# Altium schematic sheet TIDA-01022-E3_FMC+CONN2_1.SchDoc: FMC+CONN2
size 431 x 279 mm; Date: Not shown in title block; ApprovedBy: Not shown in title block; CheckedBy: Not shown in title block; Author: Not shown in title block; CompanyName: Not shown in title block; DrawnBy: Avinash N; Engineer: Not shown in title block; Organization: Not shown in title block; Address1: Not shown in title block; Address2: Not shown in title block; Address3: Not shown in title block; Address4: Not shown in title block; DocumentNumber: 1; Revision: Use project parameter SCH_Rev; SheetNumber: 19; SheetTotal: 26; PageSetup: Record=PageOptions¦CenterHorizontal=True¦CenterVertical=True¦PrintScale=1.00¦XCorrection=1.00¦YCorrection=1.00¦PrintKind=0¦BorderSize=5000000¦LeftOffset=0¦BottomOffset=0¦Orientation=2¦PaperLength=1000¦PaperWidth=1000¦Scale=100¦PaperSource=15¦PrintQuality=600¦MediaType=1¦DitherType=10¦PaperKind=Letter¦PrintScaleMode=1
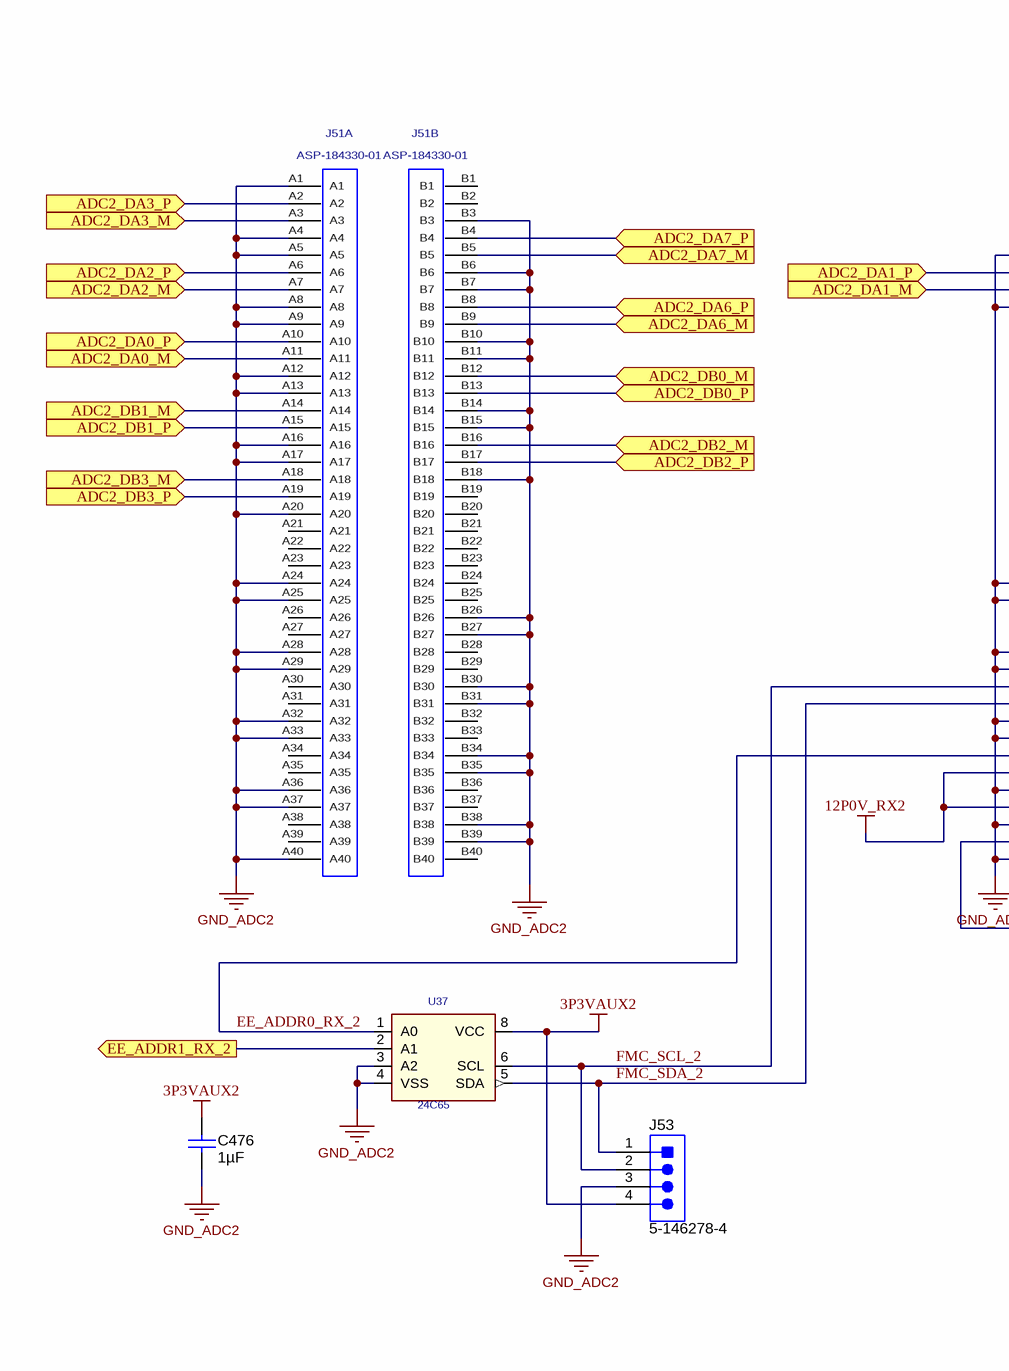
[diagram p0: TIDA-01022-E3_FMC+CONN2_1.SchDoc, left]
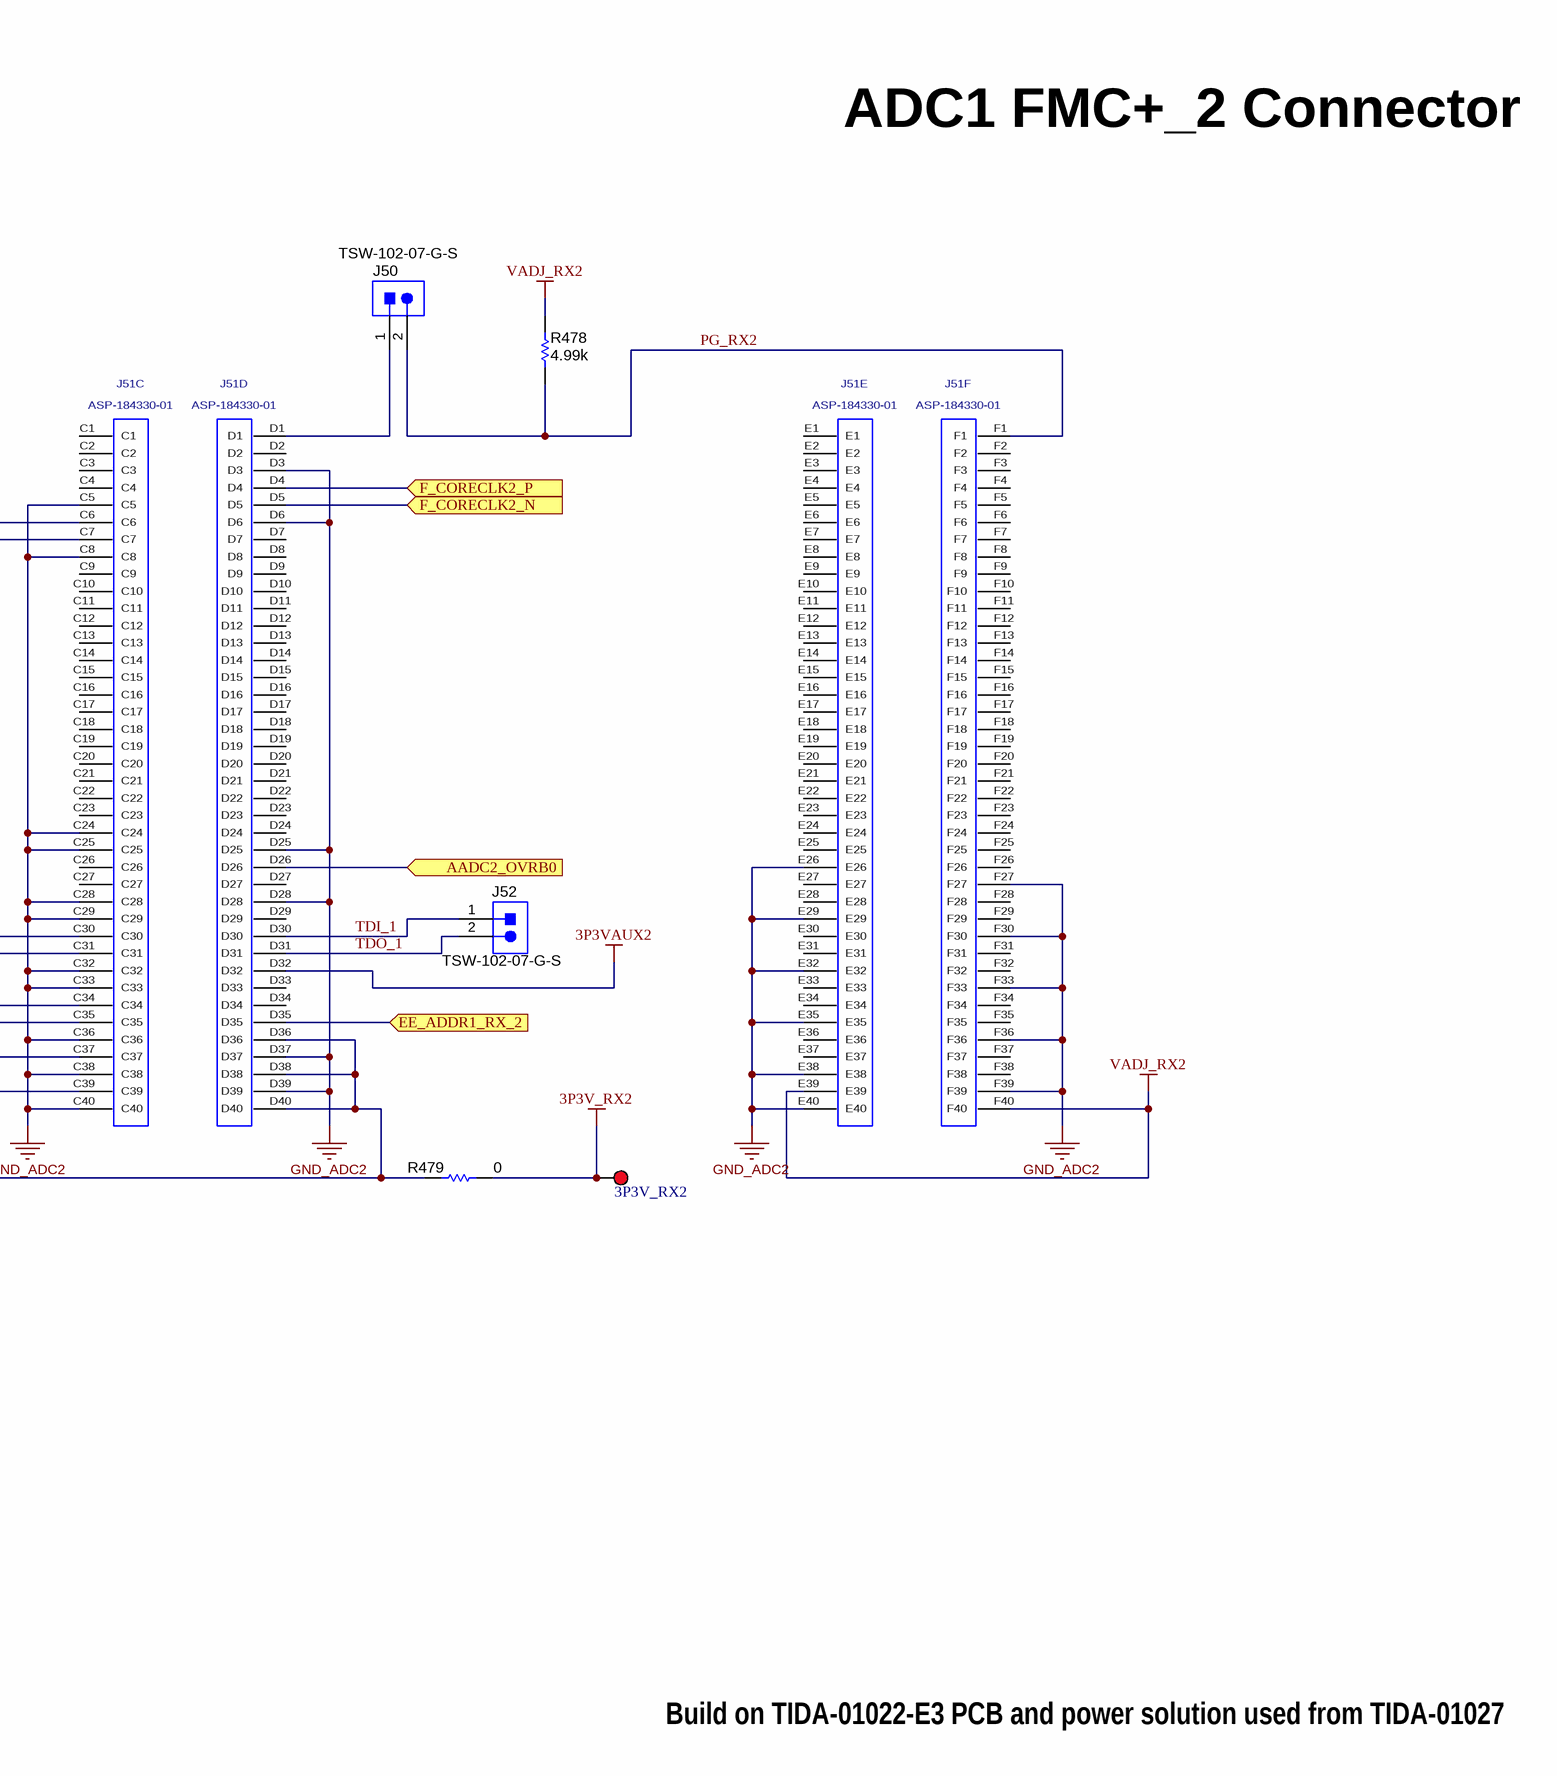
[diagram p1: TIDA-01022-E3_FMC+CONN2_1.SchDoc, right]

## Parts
3P3V_RX2  5000  [Keystone5000]  (value not drawn)
C476  ValueDisplayed: 1µF  [0603]  (hidden comment: C1608X5R1A105K080AC)
J50  TSW-102-07-G-S  [TSW-102-07-G-S]
J51  ASP-184330-01  [ASP-184330-01]  (parts A,B,C,D,E,F of 14)
J52  TSW-102-07-G-S  [TSW-102-07-G-S]
J53  5-146278-4  [TE_5-146278-4]
R478  ValueDisplayed: 4.99k  [0402]  (hidden comment: CRCW04024K99FKED)
R479  ValueDisplayed: 0  [0402]  (hidden comment: CRCW04020000Z0ED)
U37  24C65  [SOIC127P800X216-8N]

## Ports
AADC2_OVRB0 (in), ADC2_DA0_M (in), ADC2_DA0_P (in), ADC2_DA1_M (in), ADC2_DA1_P (in), ADC2_DA2_M (in), ADC2_DA2_P (in), ADC2_DA3_M (in), ADC2_DA3_P (in), ADC2_DA6_M (in), ADC2_DA6_P (in), ADC2_DA7_M (in), ADC2_DA7_P (in), ADC2_DB0_M (in), ADC2_DB0_P (in), ADC2_DB1_M (in), ADC2_DB1_P (in), ADC2_DB2_M (in), ADC2_DB2_P (in), ADC2_DB3_M (in), ADC2_DB3_P (in), EE_ADDR1_RX_2 (in), EE_ADDR1_RX_2 (out), F_CORECLK2_N (in), F_CORECLK2_P (in)

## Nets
3P3V_RX2: 3P3V_RX2.1 R479.1
3P3VAUX2: C476.1 J51.D32 J53.4 U37.8(VCC)
12P0V_RX2: J51.C35 J51.C37
GND_ADC2: C476.2 J51.A1 J51.A4 J51.A5 J51.A8 J51.A9 J51.A12 J51.A13 J51.A16 J51.A17 J51.A20 J51.A24 J51.A25 J51.A28 J51.A29 J51.A32 J51.A33 J51.A36 J51.A37 J51.A40 J51.B3 J51.B6 J51.B7 J51.B10 J51.B11 J51.B14 J51.B15 J51.B18 J51.B26 J51.B27 J51.B30 J51.B31 J51.B34 J51.B35 J51.B38 J51.B39 J51.C5 J51.C8 J51.C24 J51.C25 J51.C28 J51.C29 J51.C32 J51.C33 J51.C36 J51.C38 J51.C40 J51.D3 J51.D6 J51.D25 J51.D28 J51.D37 J51.D39 J51.E26 J51.E29 J51.E32 J51.E35 J51.E38 J51.E40 J51.F27 J51.F30 J51.F33 J51.F36 J51.F39 J53.3 U37.3(A2) U37.4(VSS)
VADJ_RX2: J51.E39 J51.F40 R478.2
AADC2_OVRB0: J51.D26 ; port AADC2_OVRB0
ADC2_DA0_M: J51.A11 ; port ADC2_DA0_M
ADC2_DA0_P: J51.A10 ; port ADC2_DA0_P
ADC2_DA1_M: J51.C7 ; port ADC2_DA1_M
ADC2_DA1_P: J51.C6 ; port ADC2_DA1_P
ADC2_DA2_M: J51.A7 ; port ADC2_DA2_M
ADC2_DA2_P: J51.A6 ; port ADC2_DA2_P
ADC2_DA3_M: J51.A3 ; port ADC2_DA3_M
ADC2_DA3_P: J51.A2 ; port ADC2_DA3_P
ADC2_DA6_M: J51.B9 ; port ADC2_DA6_M
ADC2_DA6_P: J51.B8 ; port ADC2_DA6_P
ADC2_DA7_M: J51.B5 ; port ADC2_DA7_M
ADC2_DA7_P: J51.B4 ; port ADC2_DA7_P
ADC2_DB0_M: J51.B12 ; port ADC2_DB0_M
ADC2_DB0_P: J51.B13 ; port ADC2_DB0_P
ADC2_DB1_M: J51.A14 ; port ADC2_DB1_M
ADC2_DB1_P: J51.A15 ; port ADC2_DB1_P
ADC2_DB2_M: J51.B16 ; port ADC2_DB2_M
ADC2_DB2_P: J51.B17 ; port ADC2_DB2_P
ADC2_DB3_M: J51.A18 ; port ADC2_DB3_M
ADC2_DB3_P: J51.A19 ; port ADC2_DB3_P
EE_ADDR0_RX_2: J51.C34 U37.1(A0)
EE_ADDR1_RX_2: J51.D35 U37.2(A1) ; port EE_ADDR1_RX_2
F_CORECLK2_N: J51.D5 ; port F_CORECLK2_N
F_CORECLK2_P: J51.D4 ; port F_CORECLK2_P
FMC_SCL_2: J51.C30 J53.2 U37.6(SCL)
FMC_SDA_2: J51.C31 J53.1 U37.5(SDA)
PG_RX2: J50.2 J51.F1 R478.1
TDI_1: J51.D30 J52.1
TDO_1: J51.D31 J52.2
NetJ50_1: J50.1 J51.D1
NetJ51_C39: J51.C39 J51.D36 J51.D38 J51.D40 R479.2

Not connected (* = marked no-connect by the designer): J51 A21 A22 A23 A26 A27 A30 A31 A34 A35 A38 A39 B1 B2 B19 B20 B21 B22 B23 B24 B25 B28 B29 B32 B33 B36 B37 B40 C1 C2 C3 C4 C9 C10 C11 C12 C13 C14 C15 C16 C17 C18 C19 C20 C21 C22 C23 C26 C27 D2 D7 D8 D9 D10 D11 D12 D13 D14 D15 D16 D17 D18 D19 D20 D21 D22 D23 D24 D27 D29 D33 D34 E1 E2 E3 E4 E5 E6 E7 E8 E9 E10 E11 E12 E13 E14 E15 E16 E17 E18 E19 E20 E21 E22 E23 E24 E25 E27 E28 E30 E31 E33 E34 E36 E37 F2 F3 F4 F5 F6 F7 F8 F9 F10 F11 F12 F13 F14 F15 F16 F17 F18 F19 F20 F21 F22 F23 F24 F25 F26 F28 F29 F31 F32 F34 F35 F37 F38

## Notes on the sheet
- ADC1 FMC+_2 Connector
- Build on TIDA-01022-E3 PCB and power solution used from TIDA-01027

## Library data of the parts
3P3V_RX2 = 5000: Test Point, Miniature, Red, TH; Manufacturer: Keystone; CompType: Test Point Loop; ContactFinish: Silver; Green_Lifecycle: Active; Green_REACh: Passed
C476 = C1608X5R1A105K080AC: CAP, CERM, 1 µF, 10 V, +/- 10%, X5R, 0603; Manufacturer: TDK; Polarized: N; CompType: Capacitor; Value: 1uF; U/M: EA; Cap_F: 0.000001; Tolerance_%: 10; Value1: Unknown; Value2: 10V; TaMin_C: -55; TaMax_C: 85; SizeArea_mm2: 1.28; SizeAreaWB_mm2: 4.68; SizeX_mm: 1.6; SizeY_mm: 0.8; SizeZ_mm: 1; AEC Category: Q200
J50 J52 = TSW-102-07-G-S: Header, 100mil, 2x1, Gold, TH; Manufacturer: Samtec; SymbolCreator: a0412235; Pitch_mm: 2.54; Gender: Male; Shrouded: N; Row_Count: 1; Current_A: 6.3; Voltage_V: 550; Cert_CSA: Y
J51 = ASP-184330-01: 14 ROW .050 PITCH TERMINAL ARRAY ASM.; Manufacturer: SAMTEC
J53 = 5-146278-4: Header, 100mil, 4x1, Tin, TH; Manufacturer: TE Connectivity; SymbolCreator: a0412235
R478 = CRCW04024K99FKED: RES, 4.99 k, 1%, 0.063 W, 0402; Manufacturer: Vishay-Dale; CompType: Resistor; Value: 4.99k; Res_ohm: 4990; Value_Code: 4k99; Tolerance_%: 1; Power_W: 0.063; Value2: 0.063W; VDC_V: 50; TempCo: 100 ppm/C; SizeArea_mm2: 0.5; SizeZ_mm: 0.6; EIA_Code: E96; U/M: EA; AEC Category: Q200
R479 = CRCW04020000Z0ED: RES, 0, 5%, 0.063 W, 0402; Manufacturer: Vishay-Dale; CompType: Resistor; Value: 0; Value_Code: 0000; Tolerance_%: 5; Power_W: 0.063; Value2: 0.063W; VDC_V: 50; TempCo: 200 ppm/C; SizeArea_mm2: 0.5; SizeX_mm: 1; SizeZ_mm: 0.6; EIA_Code: E24; U/M: EA; AEC Category: Q200
U37 = 24LC65: 64K I2C Smart Serial EEPROM, SOIC-8; PartNumber: 24C65T-I/SM; Manufacturer: MICROCHIP TECHNOLOGY_DNI; NC: 7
